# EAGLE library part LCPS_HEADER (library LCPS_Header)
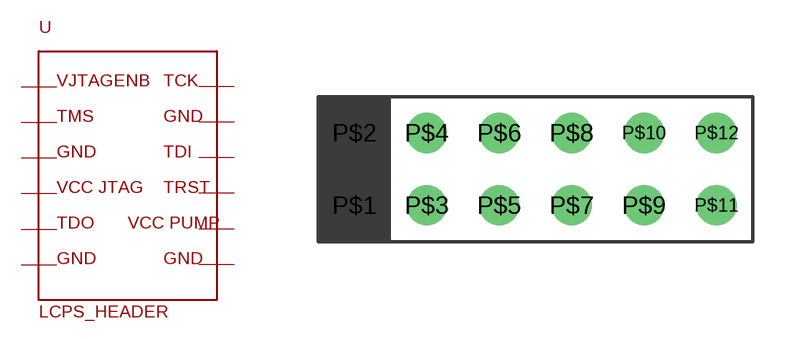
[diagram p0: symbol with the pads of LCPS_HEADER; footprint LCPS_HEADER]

Designator prefix -

## LCPS_HEADER  [LCPS_HEADER]
P$1  P$1  pas
P$2  P$2  pas
P$3  P$3  pas
P$4  P$4  pas
P$5  P$5  pas
P$6  P$6  pas
P$7  P$7  pas
P$8  P$8  pas
P$9  P$9  pas
P$10  P$10  pas
P$11  P$11  pas
P$12  P$12  pas

## Footprint LCPS_HEADER (pad centres in mm)
drill 0.9 round: P$1 -6.35,-1.27; P$2 -6.35,1.27; P$3 -3.81,-1.27; P$4 -3.81,1.27; P$5 -1.27,-1.27; P$6 -1.27,1.27; P$7 1.27,-1.27; P$8 1.27,1.27; P$9 3.81,-1.27; P$10 3.81,1.27; P$11 6.35,-1.27; P$12 6.35,1.27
